(* Logix 5000 project; controller Motion_Axis_AOIs_AMCI_RSLogix_V31 vendor 1 type 14 code 108 rev 31.11; software revision 31.02; part 5 of 7 *)
(* tags used below, declared in another part *)
   Direction_0_CW_1_CCW : BOOL;   // 0=jog CW 1=jog CCW
(* AMCI_MAJ, continued *)

ROUTINE Logic   (* ladder *)
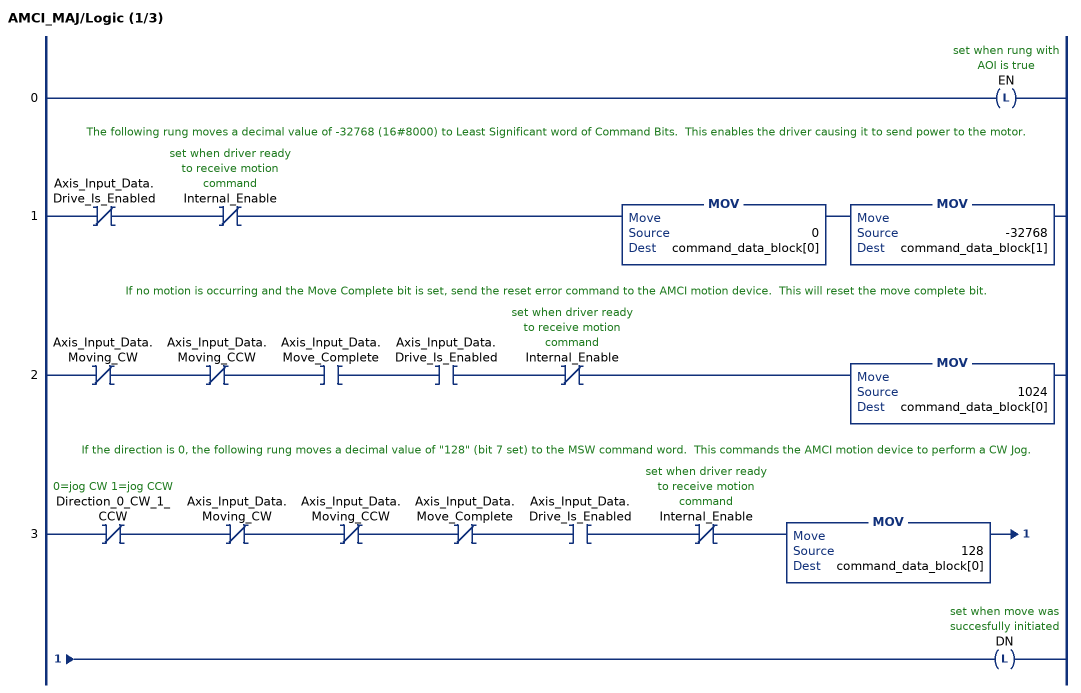
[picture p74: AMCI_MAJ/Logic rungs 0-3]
   0: OTL(EN);
   // The following rung moves a decimal value of -32768 (16#8000) to Least Significant word of Command Bits.  This enables the driver causing it to send power to the motor.
   1: XIO(Axis_Input_Data.Drive_Is_Enabled)XIO(Internal_Enable)MOV(0,command_data_block[0])MOV(-32768,command_data_block[1]);
   // If no motion is occurring and the Move Complete bit is set, send the reset error command to the AMCI motion device.  This will reset the move complete bit.
   2: XIO(Axis_Input_Data.Moving_CW)XIO(Axis_Input_Data.Moving_CCW)XIC(Axis_Input_Data.Move_Complete)XIC(Axis_Input_Data.Drive_Is_Enabled)XIO(Internal_Enable)MOV(1024,command_data_block[0]);
   // If the direction is 0, the following rung moves a decimal value of "128" (bit 7 set) to the MSW command word.  This commands the AMCI motion device to perform a CW Jog.
   3: XIO(Direction_0_CW_1_CCW)XIO(Axis_Input_Data.Moving_CW)XIO(Axis_Input_Data.Moving_CCW)XIO(Axis_Input_Data.Move_Complete)XIC(Axis_Input_Data.Drive_Is_Enabled)XIO(Internal_Enable)MOV(128,command_data_block[0])OTL(DN);
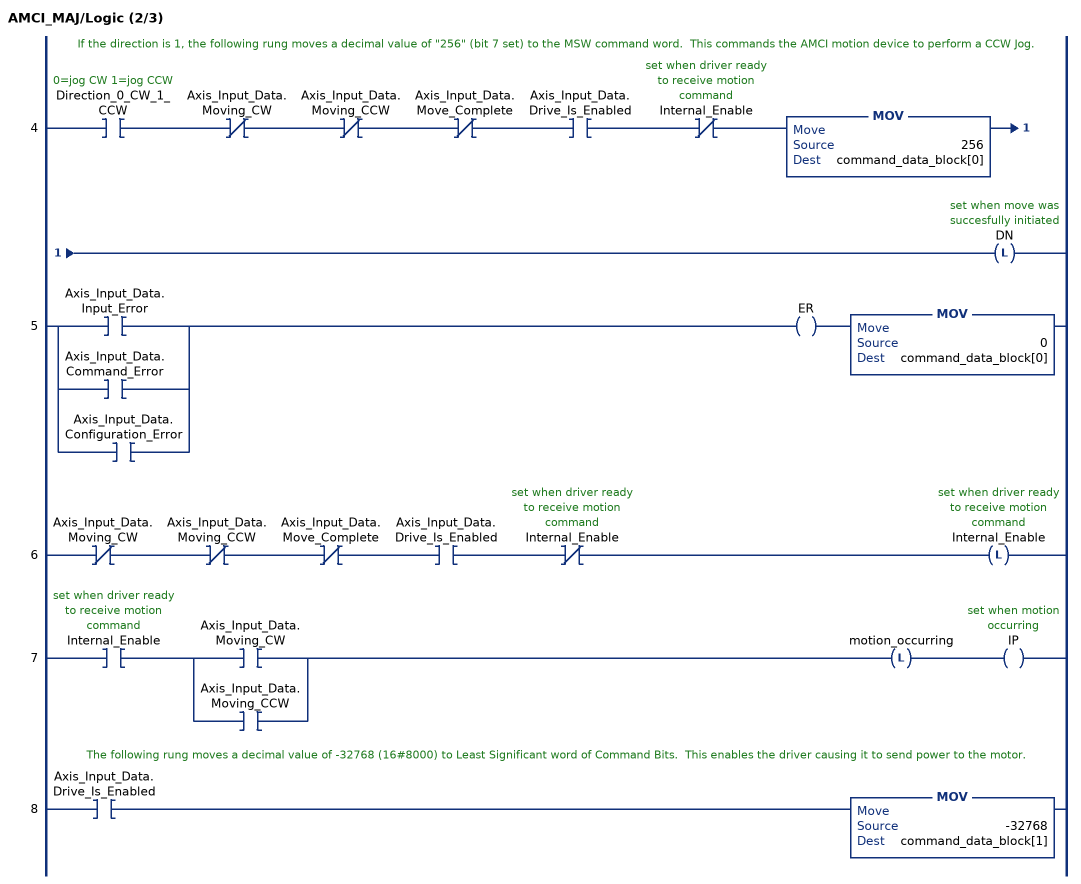
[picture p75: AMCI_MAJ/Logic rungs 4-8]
   // If the direction is 1, the following rung moves a decimal value of "256" (bit 7 set) to the MSW command word.  This commands the AMCI motion device to perform a CCW Jog.
   4: XIC(Direction_0_CW_1_CCW)XIO(Axis_Input_Data.Moving_CW)XIO(Axis_Input_Data.Moving_CCW)XIO(Axis_Input_Data.Move_Complete)XIC(Axis_Input_Data.Drive_Is_Enabled)XIO(Internal_Enable)MOV(256,command_data_block[0])OTL(DN);
   5: [XIC(Axis_Input_Data.Input_Error) ,XIC(Axis_Input_Data.Command_Error) ,XIC(Axis_Input_Data.Configuration_Error) ]OTE(ER)MOV(0,command_data_block[0]);
   6: XIO(Axis_Input_Data.Moving_CW)XIO(Axis_Input_Data.Moving_CCW)XIO(Axis_Input_Data.Move_Complete)XIC(Axis_Input_Data.Drive_Is_Enabled)XIO(Internal_Enable)OTL(Internal_Enable);
   7: XIC(Internal_Enable)[XIC(Axis_Input_Data.Moving_CW) ,XIC(Axis_Input_Data.Moving_CCW) ]OTL(motion_occurring)OTE(IP);
   // The following rung moves a decimal value of -32768 (16#8000) to Least Significant word of Command Bits.  This enables the driver causing it to send power to the motor.
   8: XIC(Axis_Input_Data.Drive_Is_Enabled)MOV(-32768,command_data_block[1]);
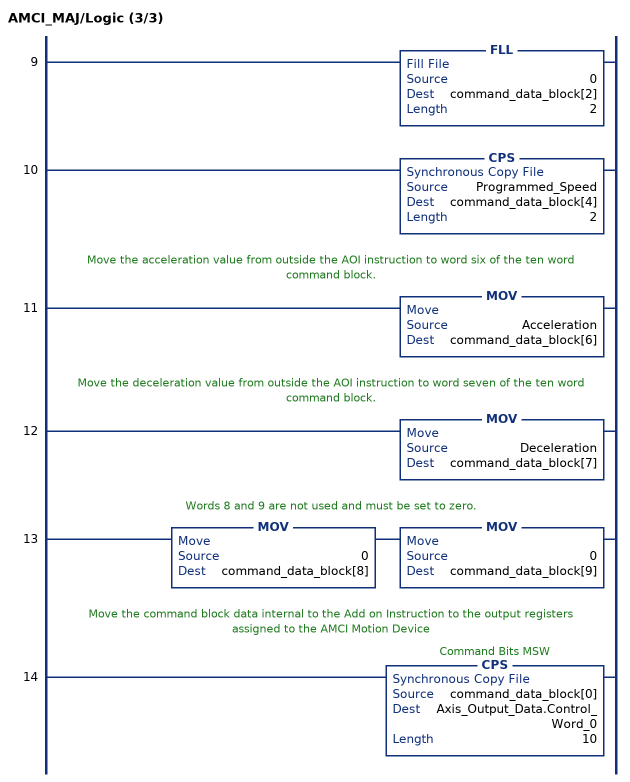
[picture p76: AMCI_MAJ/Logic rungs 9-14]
   9: FLL(0,command_data_block[2],2);
   10: CPS(Programmed_Speed,command_data_block[4],2);
   // Move the acceleration value from outside the AOI instruction to word six of the ten word command block.
   11: MOV(Acceleration,command_data_block[6]);
   // Move the deceleration value from outside the AOI instruction to word seven of the ten word command block.
   12: MOV(Deceleration,command_data_block[7]);
   // Words 8 and 9 are not used and must be set to zero.
   13: MOV(0,command_data_block[8])MOV(0,command_data_block[9]);
   // Move the command block data internal to the Add on Instruction to the output registers assigned to the AMCI Motion Device
   14: CPS(command_data_block[0],Axis_Output_Data.Control_Word_0,10);
END_ROUTINE
END_ADD_ON_INSTRUCTION

ADD_ON_INSTRUCTION AMCI_MAM   (* revision 2.0, vendor AMCI, ExecuteEnableInFalse *)
// Absolute and Relative Moves
// Revision note:
// 11/22/22 Initial release of AOI
// 3/6/23 Added logic so that the PC output bit turns on for short moves.  It will also be set for moves of zero steps.
// Help:
// MOTION AXIS MOVE: Performs Absolute or Relative Moves
// AXIS INPUT DATA:  Input data from AMCI motion device.   Uses the AMCI_Motion_Axis_Input_Data User Defined Data Type.
// AXIS OUTPUT DATA; Output data from the AOI to the AMCI motion device.   Uses the AMCI_Motion_Axis_Output_Data User Defined Data Type.
// MOVE TYPE: 0 = Absolute Move, 1 = Relative Move
// POSITION OR DISTANCE: Target Position of the Absolute Move or the distance to move of a Relative                                              Move.
// PROGRAMMED SPEED: Speed of move in units of steps / sec
// ACCELERATION: Acceleration Rate in units of steps / sec / ms
// DECELERATION:  Deceleration Rate in units of steps / sec / ms
// EN (Enable) Set when rung is true, Reset when rung is false
// DN (Done) Set when command is sent to the motion device.  Reset when the rung is false.
// ER (Error) Set when a command or input error failed to clear.  Reset when the rung is false.
// IP (In Process) Set when motion is occurring.   Reset when motion stops or the rung goes false.
// PC (Process Complete) Set when the move is complete.  Reset the next time the rung with the AOI transitions                                       from False to True.
VAR_IN_OUT
   Axis_Input_Data : AMCI_Motion_Axis_Input_Data; {required}
   Axis_Output_Data : AMCI_Motion_Axis_Output_Data; {required}
END_VAR
VAR_INPUT
   Type_0_for_standard_1_for_indexed : BOOL;
   Move_type_0_Absolute_1_Relative : BOOL; {required}   // 0=absolute 1=relative
   Position_or_Distance : DINT; {required}
   Programmed_Speed : DINT; {required}
   Acceleration : INT; {required}
   Deceleration : INT; {required}
END_VAR
VAR_OUTPUT
   EN : BOOL; {visible}   // set when rung with AOI is true
   DN : BOOL; {access Read Only, visible}   // set when move was succesfully initiated
   ER : BOOL; {visible}   // set when input error, command error, or configuration error
   IP : BOOL; {visible}   // set when motion occurring
   PC : BOOL; {visible}   // set when process complete
END_VAR
VAR
   command_data_block : INT[10];
        [2]   // Upper Target Position
        [1]   // Command Bits LSW
        [3]   // Lower Target Position
        [5]   // Lower Programmed Speed
        [4]   // Upper Programmed Speed
        [0]   // Command Bits MSW
   motion_occurring : BOOL; {access None}
   Internal_Enable : BOOL; {access None}   // set when driver ready to receive motion command
END_VAR

ROUTINE EnableInFalse   (* ladder *)
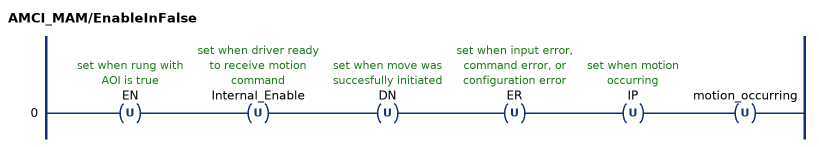
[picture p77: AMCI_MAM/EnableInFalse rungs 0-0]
   0: OTU(EN)OTU(Internal_Enable)OTU(DN)OTU(ER)OTU(IP)OTU(motion_occurring);
END_ROUTINE

ROUTINE Logic   (* ladder *)
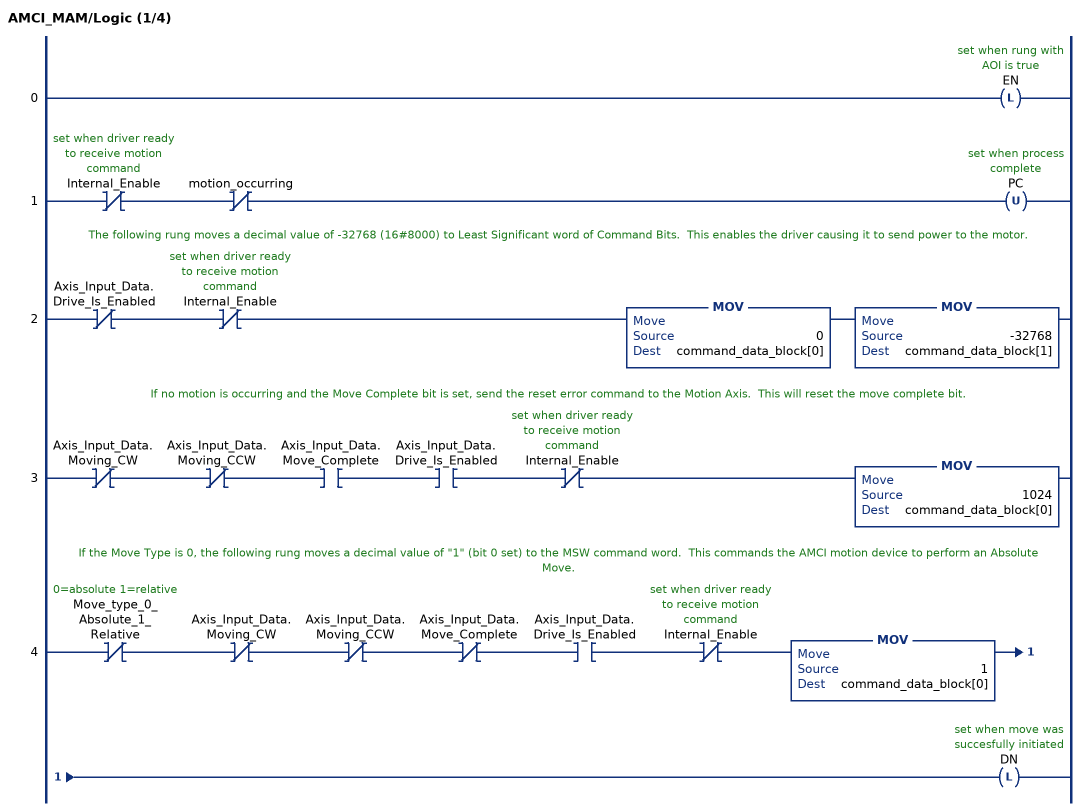
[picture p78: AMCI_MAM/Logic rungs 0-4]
   0: OTL(EN);
   1: XIO(Internal_Enable)XIO(motion_occurring)OTU(PC);
   // The following rung moves a decimal value of -32768 (16#8000) to Least Significant word of Command Bits.  This enables the driver causing it to send power to the motor.
   2: XIO(Axis_Input_Data.Drive_Is_Enabled)XIO(Internal_Enable)MOV(0,command_data_block[0])MOV(-32768,command_data_block[1]);
   // If no motion is occurring and the Move Complete bit is set, send the reset error command to the Motion Axis.  This will reset the move complete bit.
   3: XIO(Axis_Input_Data.Moving_CW)XIO(Axis_Input_Data.Moving_CCW)XIC(Axis_Input_Data.Move_Complete)XIC(Axis_Input_Data.Drive_Is_Enabled)XIO(Internal_Enable)MOV(1024,command_data_block[0]);
   // If the Move Type is 0, the following rung moves a decimal value of "1" (bit 0 set) to the MSW command word.  This commands the AMCI motion device to perform an Absolute Move.
   4: XIO(Move_type_0_Absolute_1_Relative)XIO(Axis_Input_Data.Moving_CW)XIO(Axis_Input_Data.Moving_CCW)XIO(Axis_Input_Data.Move_Complete)XIC(Axis_Input_Data.Drive_Is_Enabled)XIO(Internal_Enable)MOV(1,command_data_block[0])OTL(DN);
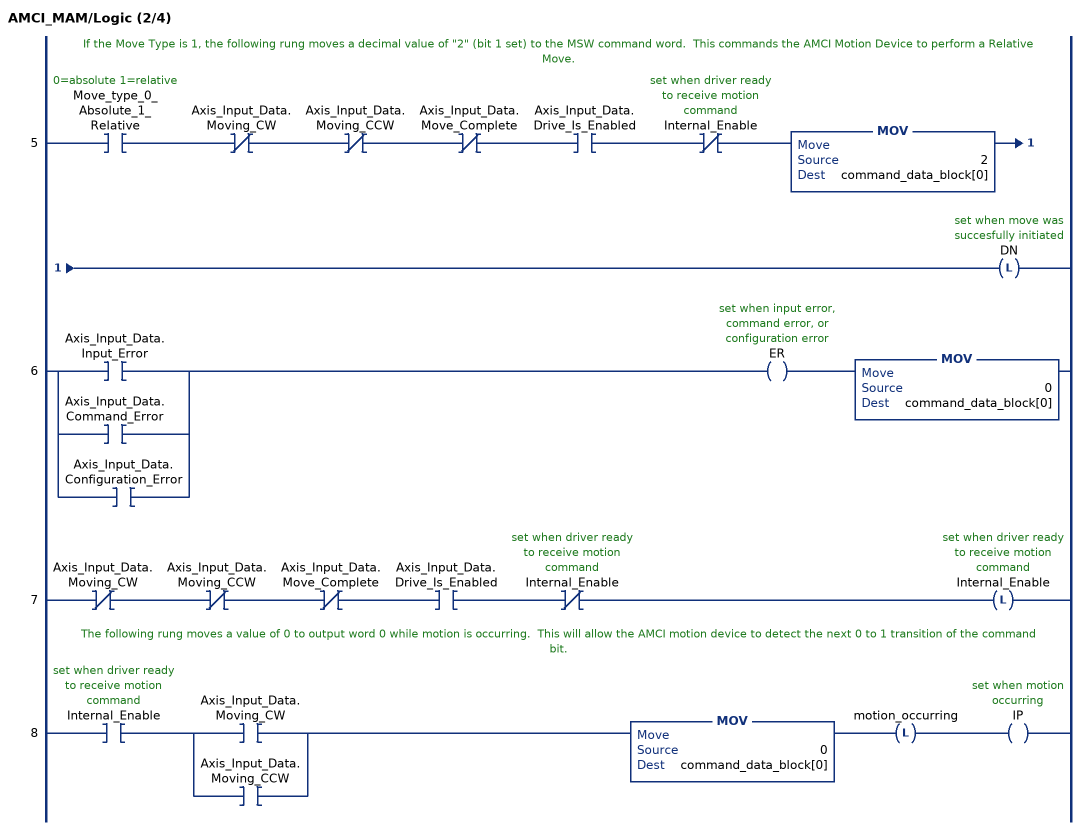
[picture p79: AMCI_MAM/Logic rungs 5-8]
   // If the Move Type is 1, the following rung moves a decimal value of "2" (bit 1 set) to the MSW command word.  This commands the AMCI Motion Device to perform a Relative Move.
   5: XIC(Move_type_0_Absolute_1_Relative)XIO(Axis_Input_Data.Moving_CW)XIO(Axis_Input_Data.Moving_CCW)XIO(Axis_Input_Data.Move_Complete)XIC(Axis_Input_Data.Drive_Is_Enabled)XIO(Internal_Enable)MOV(2,command_data_block[0])OTL(DN);
   6: [XIC(Axis_Input_Data.Input_Error) ,XIC(Axis_Input_Data.Command_Error) ,XIC(Axis_Input_Data.Configuration_Error) ]OTE(ER)MOV(0,command_data_block[0]);
   7: XIO(Axis_Input_Data.Moving_CW)XIO(Axis_Input_Data.Moving_CCW)XIO(Axis_Input_Data.Move_Complete)XIC(Axis_Input_Data.Drive_Is_Enabled)XIO(Internal_Enable)OTL(Internal_Enable);
   // The following rung moves a value of 0 to output word 0 while motion is occurring.  This will allow the AMCI motion device to detect the next 0 to 1 transition of the command bit.
   8: XIC(Internal_Enable)[XIC(Axis_Input_Data.Moving_CW) ,XIC(Axis_Input_Data.Moving_CCW) ]MOV(0,command_data_block[0])OTL(motion_occurring)OTE(IP);
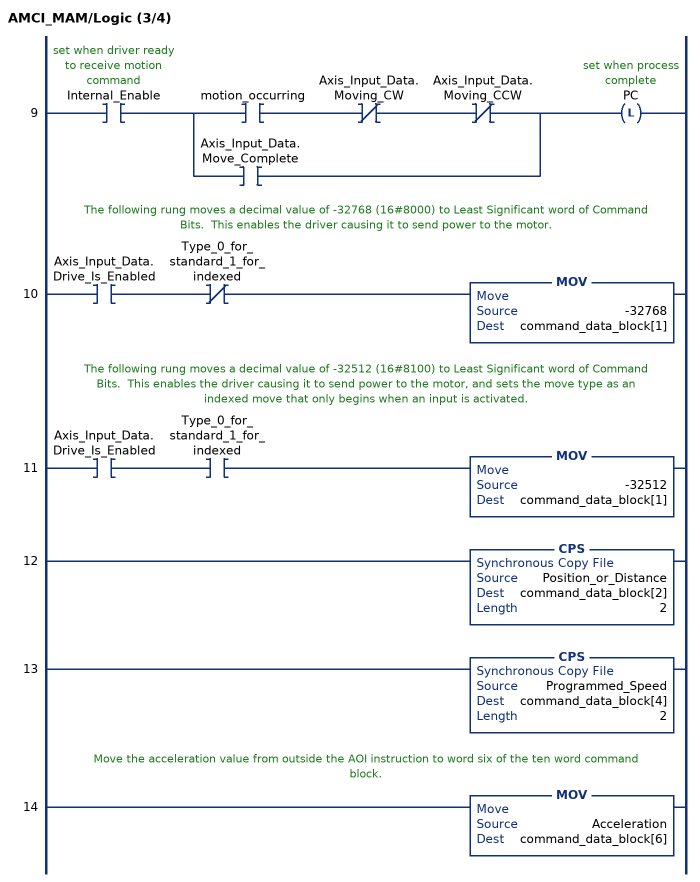
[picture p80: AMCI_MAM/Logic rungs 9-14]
   9: XIC(Internal_Enable)[XIC(motion_occurring) XIO(Axis_Input_Data.Moving_CW) XIO(Axis_Input_Data.Moving_CCW) ,XIC(Axis_Input_Data.Move_Complete) ]OTL(PC);
   // The following rung moves a decimal value of -32768 (16#8000) to Least Significant word of Command Bits.  This enables the driver causing it to send power to the motor.
   10: XIC(Axis_Input_Data.Drive_Is_Enabled)XIO(Type_0_for_standard_1_for_indexed)MOV(-32768,command_data_block[1]);
   // The following rung moves a decimal value of -32512 (16#8100) to Least Significant word of Command Bits.  This enables the driver causing it to send power to the motor, and sets the move type as an indexed move that only begins when an input is activated.
   11: XIC(Axis_Input_Data.Drive_Is_Enabled)XIC(Type_0_for_standard_1_for_indexed)MOV(-32512,command_data_block[1]);
   12: CPS(Position_or_Distance,command_data_block[2],2);
   13: CPS(Programmed_Speed,command_data_block[4],2);
   // Move the acceleration value from outside the AOI instruction to word six of the ten word command block.
   14: MOV(Acceleration,command_data_block[6]);
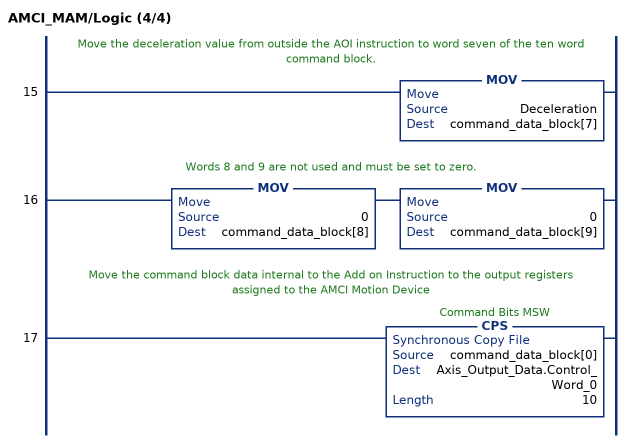
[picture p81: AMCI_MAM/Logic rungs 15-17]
   // Move the deceleration value from outside the AOI instruction to word seven of the ten word command block.
   15: MOV(Deceleration,command_data_block[7]);
   // Words 8 and 9 are not used and must be set to zero.
   16: MOV(0,command_data_block[8])MOV(0,command_data_block[9]);
   // Move the command block data internal to the Add on Instruction to the output registers assigned to the AMCI Motion Device
   17: CPS(command_data_block[0],Axis_Output_Data.Control_Word_0,10);
END_ROUTINE
END_ADD_ON_INSTRUCTION

ADD_ON_INSTRUCTION AMCI_MAS   (* revision 2.0, vendor AMCI, ExecuteEnableInFalse *)
// AMCI Motion Axis Stop
// Revision note:
// 3/12/2024 Version 2: Logic added to keep the driver in its current state, either enabled or disabled.
// Help:
// MOTION AXIS STOP: Stops motion that is occurring.
// AXIS INPUT DATA:  Input data from AMCI motion device.   Uses the AMCI_Motion_Axis_Input_Data User Defined Data Type.
// AXIS OUTPUT DATA; Output data from the AOI to the AMCI motion device.   Uses the AMCI_Motion_Axis_Output_Data User Defined Data Type.
// EN (Enable) Set when rung is true, Reset when rung is false
// DN (Done) Set when command is sent to the motion device.  Reset when the rung is false.
// ER (Error) Set when a command or input error failed to clear.  Reset when the rung is false.
// IP (In Process) Set when axis is decelerating.   Reset when motion stops or the rung goes false.
// PC (Process Complete) Set when motion has stopped.   Reset the next time the rung with the AOI transitions                                      from false to true.
VAR_IN_OUT
   Axis_Input_Data : AMCI_Motion_Axis_Input_Data; {required}
   Axis_Output_Data : AMCI_Motion_Axis_Output_Data; {required}
END_VAR
VAR_OUTPUT
   EN : BOOL; {visible}   // set when rung with AOI is true
   DN : BOOL; {access Read Only, visible}   // set when hold was succesfully initiated
   ER : BOOL; {visible}
   IP : BOOL; {visible}   // set when decelerating
   PC : BOOL; {visible}   // set when process complete
END_VAR
VAR
   command_data_block : INT[10];
        [5]   // Lower Programmed Speed
        [0]   // Command Bits MSW
        [2]   // Upper Target Position
        [4]   // Upper Programmed Speed
        [1]   // Command Bits LSW
        [3]   // Lower Target Position
   internal_enable : BOOL; {access None}   // set when driver ready to receive command
END_VAR

ROUTINE EnableInFalse   (* ladder *)
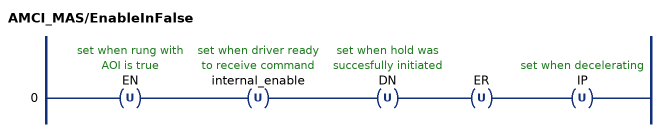
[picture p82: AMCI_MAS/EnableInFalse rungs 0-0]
   0: OTU(EN)OTU(internal_enable)OTU(DN)OTU(ER)OTU(IP);
END_ROUTINE

ROUTINE Logic   (* ladder *)
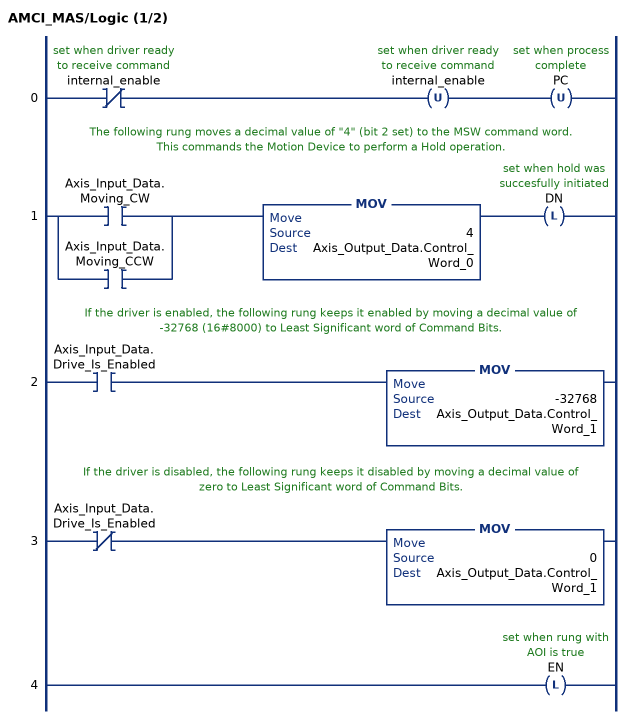
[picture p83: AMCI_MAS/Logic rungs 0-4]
   0: XIO(internal_enable)OTU(internal_enable)OTU(PC);
   // The following rung moves a decimal value of "4" (bit 2 set) to the MSW command word.  This commands the Motion Device to perform a Hold operation.
   1: [XIC(Axis_Input_Data.Moving_CW) ,XIC(Axis_Input_Data.Moving_CCW) ]MOV(4,Axis_Output_Data.Control_Word_0)OTL(DN);
   // If the driver is enabled, the following rung keeps it enabled by moving a decimal value of -32768 (16#8000) to Least Significant word of Command Bits.
   2: XIC(Axis_Input_Data.Drive_Is_Enabled)MOV(-32768,Axis_Output_Data.Control_Word_1);
   // If the driver is disabled, the following rung keeps it disabled by moving a decimal value of zero to Least Significant word of Command Bits.
   3: XIO(Axis_Input_Data.Drive_Is_Enabled)MOV(0,Axis_Output_Data.Control_Word_1);
   4: OTL(EN);
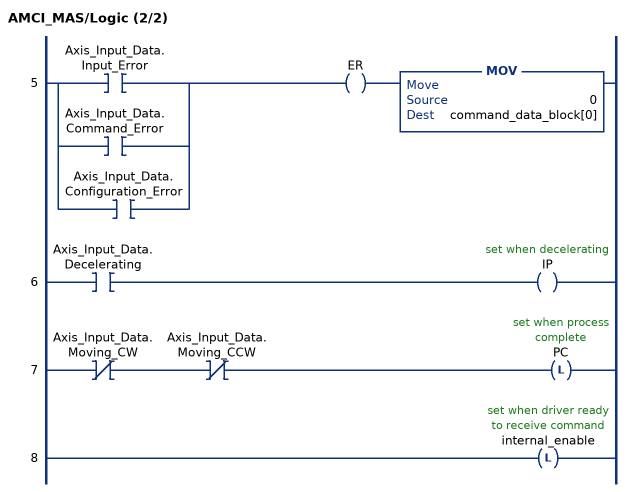
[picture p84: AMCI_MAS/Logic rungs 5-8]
   5: [XIC(Axis_Input_Data.Input_Error) ,XIC(Axis_Input_Data.Command_Error) ,XIC(Axis_Input_Data.Configuration_Error) ]OTE(ER)MOV(0,command_data_block[0]);
   6: XIC(Axis_Input_Data.Decelerating)OTE(IP);
   7: XIO(Axis_Input_Data.Moving_CW)XIO(Axis_Input_Data.Moving_CCW)OTL(PC);
   8: OTL(internal_enable);
END_ROUTINE
END_ADD_ON_INSTRUCTION

ADD_ON_INSTRUCTION AMCI_MRP   (* revision 2.1, vendor AMCI, ExecuteEnableInFalse *)
// AMCI Preset Motor Position
// Revision note:
// 3/6/23: Added Save to Flash bit
// 11/17/23 V2.1 Reset output word 0 to 0 when the rung goes false.
// Help:
// MOTION REDEFINE POSITION: Sets the Current Motor Position to the value in the Position field of the AOI.  This command will also reset the Position Invalid status bit.
// Note: This instruction will maintain the motion device’s current enabled state.  That is, if the device is enabled,
//            it will remain enabled.  If it is disabled, it will remain disabled.
// AXIS INPUT DATA:  Input data from AMCI motion device.   Uses the AMCI_Motion_Axis_Input_Data User Defined Data Type.
// AXIS OUTPUT DATA; Output data from the AOI to the AMCI motion device.   Uses the AMCI_Motion_Axis_Output_Data User Defined Data Type.
// POSITION: Position to which the Motor Position is to be set.
// SAVE_IN_FLASH_0_NO_1_YES:   Saves the offset in the flash memory.    Only used on the SVXXXE2 units.  Must be zero on all other units.
// EN (Enable) Set when rung is true, Reset when rung is false
// DN (Done) Set when command is sent to the motion device.  Reset when the rung is false.
// ER (Error) Set when a command or input error failed to clear.  Reset when the rung is false.
VAR_IN_OUT
   Axis_Input_Data : AMCI_Motion_Axis_Input_Data; {required}
   Axis_Output_Data : AMCI_Motion_Axis_Output_Data; {required}
END_VAR
VAR_INPUT
   Position : DINT; {required}
   Save_In_Flash_0_no_1_yes : BOOL; {required}
END_VAR
VAR_OUTPUT
   EN : BOOL; {visible}   // set when rung with AOI is true
   DN : BOOL; {access Read Only, visible}   // set when preset motor position command sent to motion axis
   ER : BOOL; {access Read Only, visible}   // set when input, command, or configuraiton error
END_VAR
VAR
   command_data_block : INT[10];
        [2]   // Upper Target Position
        [4]   // Upper Programmed Speed
        [1]   // Command Bits LSW
        [3]   // Lower Target Position
        [5]   // Lower Programmed Speed
        [0]   // Command Bits MSW
END_VAR

ROUTINE EnableInFalse   (* ladder *)
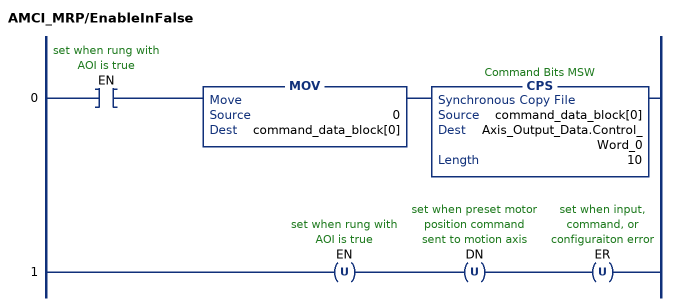
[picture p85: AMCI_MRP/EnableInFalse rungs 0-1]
   0: XIC(EN)MOV(0,command_data_block[0])CPS(command_data_block[0],Axis_Output_Data.Control_Word_0,10);
   1: OTU(EN)OTU(DN)OTU(ER);
END_ROUTINE

ROUTINE Logic   (* ladder *)
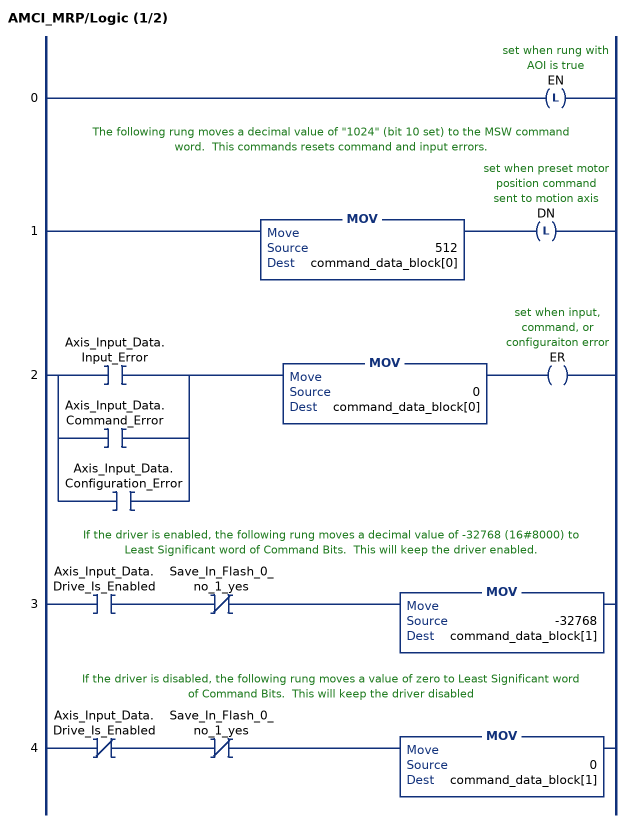
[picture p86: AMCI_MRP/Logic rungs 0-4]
   0: OTL(EN);
   // The following rung moves a decimal value of "1024" (bit 10 set) to the MSW command word.  This commands resets command and input errors.
   1: MOV(512,command_data_block[0])OTL(DN);
   2: [XIC(Axis_Input_Data.Input_Error) ,XIC(Axis_Input_Data.Command_Error) ,XIC(Axis_Input_Data.Configuration_Error) ]MOV(0,command_data_block[0])OTE(ER);
   // If the driver is enabled, the following rung moves a decimal value of -32768 (16#8000) to Least Significant word of Command Bits.  This will keep the driver enabled.
   3: XIC(Axis_Input_Data.Drive_Is_Enabled)XIO(Save_In_Flash_0_no_1_yes)MOV(-32768,command_data_block[1]);
   // If the driver is disabled, the following rung moves a value of zero to Least Significant word of Command Bits.  This will keep the driver disabled
   4: XIO(Axis_Input_Data.Drive_Is_Enabled)XIO(Save_In_Flash_0_no_1_yes)MOV(0,command_data_block[1]);
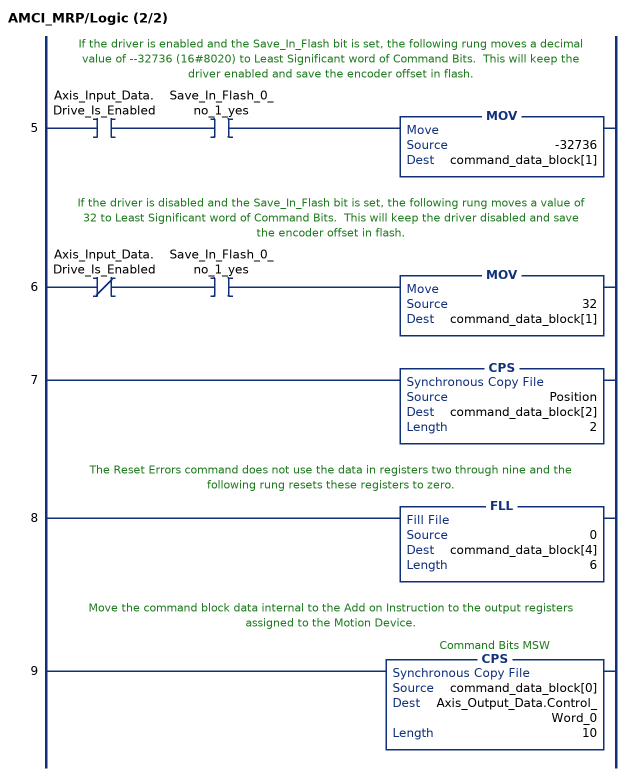
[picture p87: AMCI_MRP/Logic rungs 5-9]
   // If the driver is enabled and the Save_In_Flash bit is set, the following rung moves a decimal value of --32736 (16#8020) to Least Significant word of Command Bits.  This will keep the driver enabled and save the encoder offset in flash.
   5: XIC(Axis_Input_Data.Drive_Is_Enabled)XIC(Save_In_Flash_0_no_1_yes)MOV(-32736,command_data_block[1]);
   // If the driver is disabled and the Save_In_Flash bit is set, the following rung moves a value of 32 to Least Significant word of Command Bits.  This will keep the driver disabled and save the encoder offset in flash.
   6: XIO(Axis_Input_Data.Drive_Is_Enabled)XIC(Save_In_Flash_0_no_1_yes)MOV(32,command_data_block[1]);
   7: CPS(Position,command_data_block[2],2);
   // The Reset Errors command does not use the data in registers two through nine and the following rung resets these registers to zero.
   8: FLL(0,command_data_block[4],6);
   // Move the command block data internal to the Add on Instruction to the output registers assigned to the Motion Device.
   9: CPS(command_data_block[0],Axis_Output_Data.Control_Word_0,10);
END_ROUTINE
END_ADD_ON_INSTRUCTION

ADD_ON_INSTRUCTION AMCI_MSF_Disable   (* revision 1.0, vendor AMCI, ExecuteEnableInFalse *)
// AMCI Disable Driver
// Help:
// MSF_DISABLE:   Removes power from the motor.
// This instruction must only be used to change the existing enabled / disabled state of the AMCI motion device.  It MUST NOT  be used in an unconditional rung because it will interfere with the other instructions sending data to the motion device
// AXIS INPUT DATA:  Input data from AMCI motion device.   Uses the AMCI_Motion_Axis_Input_Data User Defined Data Type.
// AXIS OUTPUT DATA; Output data from the AOI to the AMCI motion device.   Uses the AMCI_Motion_Axis_Output_Data User Defined Data Type.
// EN (Enable) Set when rung is true, Reset when rung is false
// DN (Done) Set when command is sent to the motion device.  Reset when the rung is false.
VAR_IN_OUT
   Axis_Input_Data : AMCI_Motion_Axis_Input_Data; {required}
   Axis_Output_Data : AMCI_Motion_Axis_Output_Data; {required}
END_VAR
VAR_OUTPUT
   EN : BOOL; {visible}   // set when rung with AOI is true
   DN : BOOL; {access Read Only, visible}   // set when reset error command sent to motion axis
END_VAR
VAR
   command_data_block : INT[10];
        [5]   // Lower Programmed Speed
        [0]   // Command Bits MSW
        [2]   // Upper Target Position
        [4]   // Upper Programmed Speed
        [1]   // Command Bits LSW
        [3]   // Lower Target Position
END_VAR

ROUTINE EnableInFalse   (* ladder *)
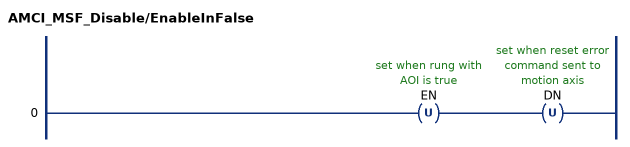
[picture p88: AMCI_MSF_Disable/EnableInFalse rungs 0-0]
   0: OTU(EN)OTU(DN);
END_ROUTINE

ROUTINE Logic   (* ladder *)
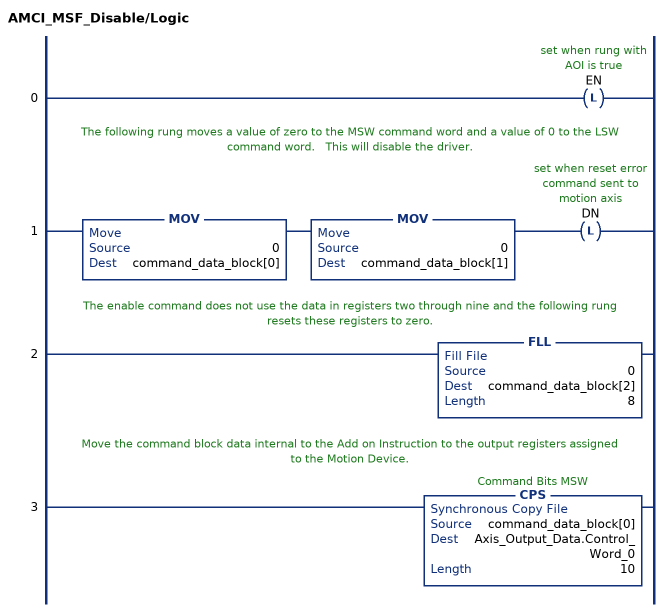
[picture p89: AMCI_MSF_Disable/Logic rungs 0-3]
   0: OTL(EN);
   // The following rung moves a value of zero to the MSW command word and a value of 0 to the LSW command word.   This will disable the driver.
   1: MOV(0,command_data_block[0])MOV(0,command_data_block[1])OTL(DN);
   // The enable command does not use the data in registers two through nine and the following rung resets these registers to zero.
   2: FLL(0,command_data_block[2],8);
   // Move the command block data internal to the Add on Instruction to the output registers assigned to the Motion Device.
   3: CPS(command_data_block[0],Axis_Output_Data.Control_Word_0,10);
END_ROUTINE
END_ADD_ON_INSTRUCTION

ADD_ON_INSTRUCTION AMCI_MSO_and_Preset_to_Absolute_Encoder   (* revision 2.0, vendor AMCI, ExecuteEnableInFalse *)
// Enables and sets the motor position to the absolute encoder position.   Only for AMCI SMDXXE2 with Absolute Encoders.
// Revision note:
// 3/8/23: Revision 2.  Changed the name to MSO and Preset to Absolute Encoder.   No change the functionality.
// Help:
// This AOI will only work with SMDXXE2 units with an absolute encoder.  This AOI WILL NOT WORK with SDXXXXXE2 or SVXXXE2 units.
// This instruction enables the motion device before presetting the motor position to the absolute encoder position.
// AXIS INPUT DATA:  Input data from AMCI motion device.   Uses the AMCI_Motion_Axis_Input_Data User Defined Data Type.
// AXIS OUTPUT DATA; Output data from the AOI to the AMCI motion device.   Uses the AMCI_Motion_Axis_Output_Data User Defined Data Type.
// EN (Enable) Set when rung is true, Reset when rung is false
// DN (Done) Set when command is sent to the motion device.  Reset when the rung is false.
// ER (Error) Set when a command or input error failed to clear.  Reset when the rung is false.
VAR_IN_OUT
   Axis_Input_Data : AMCI_Motion_Axis_Input_Data; {required}
   Axis_Output_Data : AMCI_Motion_Axis_Output_Data; {required}
END_VAR
VAR_OUTPUT
   EN : BOOL; {visible}   // set when rung with AOI is true
   DN : BOOL; {access Read Only, visible}   // set when preset motor position command sent to motion axis
   ER : BOOL; {access Read Only, visible}   // set when input, command, or configuraiton error
END_VAR
VAR
   command_data_block : INT[10];
        [5]   // Lower Programmed Speed
        [0]   // Command Bits MSW
        [2]   // Upper Target Position
        [4]   // Upper Programmed Speed
        [1]   // Command Bits LSW
        [3]   // Lower Target Position
   enable_timer : TIMER := (PRE := 100); {access None}
   driver_enabled : DINT; {access None}
END_VAR

ROUTINE EnableInFalse   (* ladder *)
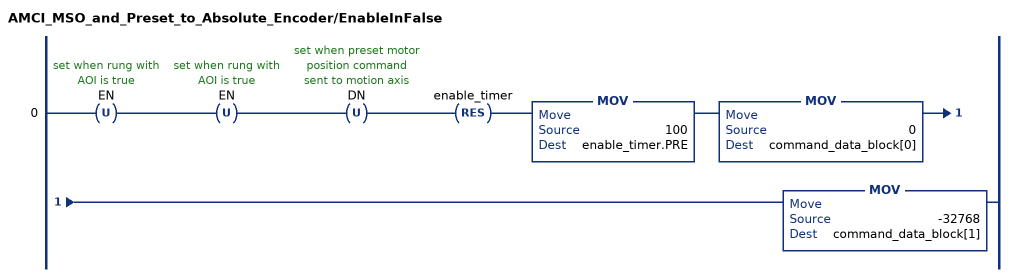
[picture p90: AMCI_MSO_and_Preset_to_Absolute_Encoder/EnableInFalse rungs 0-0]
   0: OTU(EN)OTU(EN)OTU(DN)RES(enable_timer)MOV(100,enable_timer.PRE)MOV(0,command_data_block[0])MOV(-32768,command_data_block[1]);
END_ROUTINE

ROUTINE Logic   (* ladder *)
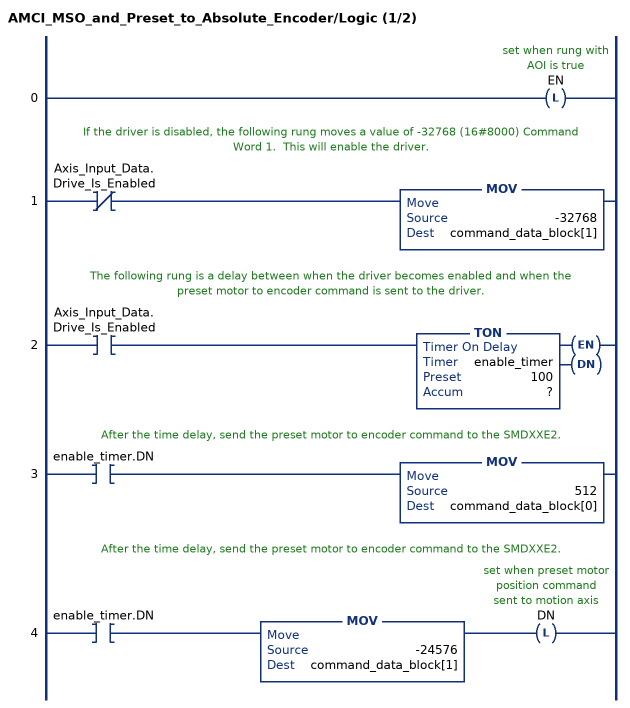
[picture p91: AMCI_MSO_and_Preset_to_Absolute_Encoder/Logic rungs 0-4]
   0: OTL(EN);
   // If the driver is disabled, the following rung moves a value of -32768 (16#8000) Command Word 1.  This will enable the driver.
   1: XIO(Axis_Input_Data.Drive_Is_Enabled)MOV(-32768,command_data_block[1]);
   // The following rung is a delay between when the driver becomes enabled and when the preset motor to encoder command is sent to the driver.
   2: XIC(Axis_Input_Data.Drive_Is_Enabled)TON(enable_timer,?,?);
   // After the time delay, send the preset motor to encoder command to the SMDXXE2.
   3: XIC(enable_timer.DN)MOV(512,command_data_block[0]);
   // After the time delay, send the preset motor to encoder command to the SMDXXE2.
   4: XIC(enable_timer.DN)MOV(-24576,command_data_block[1])OTL(DN);
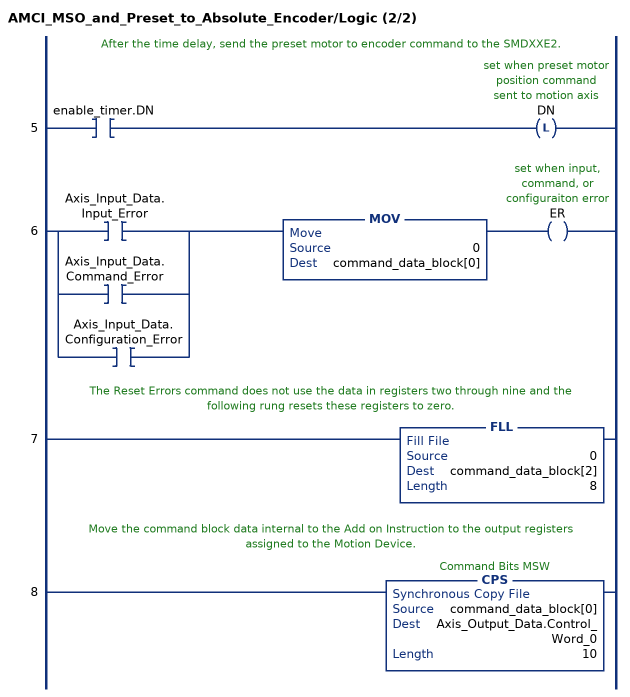
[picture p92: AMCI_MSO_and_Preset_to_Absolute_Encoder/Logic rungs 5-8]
   // After the time delay, send the preset motor to encoder command to the SMDXXE2.
   5: XIC(enable_timer.DN)OTL(DN);
   6: [XIC(Axis_Input_Data.Input_Error) ,XIC(Axis_Input_Data.Command_Error) ,XIC(Axis_Input_Data.Configuration_Error) ]MOV(0,command_data_block[0])OTE(ER);
   // The Reset Errors command does not use the data in registers two through nine and the following rung resets these registers to zero.
   7: FLL(0,command_data_block[2],8);
   // Move the command block data internal to the Add on Instruction to the output registers assigned to the Motion Device.
   8: CPS(command_data_block[0],Axis_Output_Data.Control_Word_0,10);
END_ROUTINE
END_ADD_ON_INSTRUCTION
